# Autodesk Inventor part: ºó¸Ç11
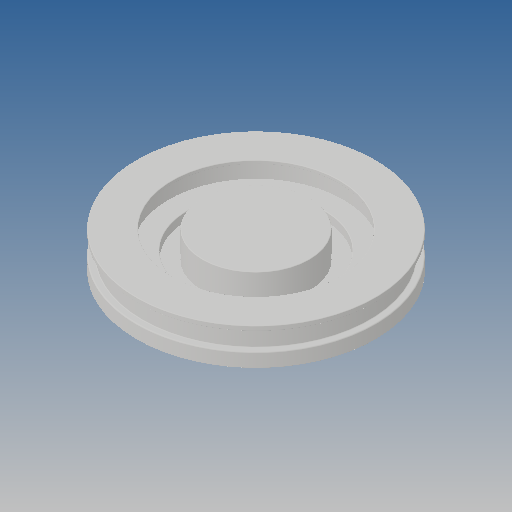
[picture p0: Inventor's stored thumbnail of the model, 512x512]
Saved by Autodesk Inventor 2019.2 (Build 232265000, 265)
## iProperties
Created: 2013-07
Part Number: ºó¸Ç11
Material: Ogólny
Document SubType Name: Modeling
Designer: CADENGINEERING4
Density: 1 g/cm^3
Appearance: Domyślna
Author: CADENGINEERING4
Revision Number: ÈÎºÎ
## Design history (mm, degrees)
feature "Ðý×ª1"
node "Bryła1"
